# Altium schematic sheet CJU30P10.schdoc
size 127 x 101 mm
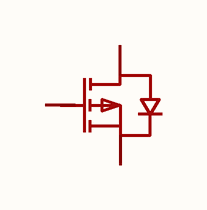
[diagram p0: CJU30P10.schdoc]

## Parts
Q?  cju30p10  [TO-252-2_L6.6-W6.1-P4.57-LS10.1-BL]  (value not drawn)

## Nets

Not connected (* = marked no-connect by the designer): Q? 1(G) 2(S) 3(D)

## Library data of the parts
Q? = cju30p10: 数量:1个P沟道;漏源电压(Vdss):100V;连续漏极电流(Id):30A;导通电阻(RDS(on)):55mΩ@4.5V;耗散功率(Pd):108W;阈值电压(Vgs(th)):2.5V;; Manufacturer: CJ(江苏长电/长晶); AddInBom: yes; ModelId: b8490bd177664f85abc7dca42f3ee0d2; ModelTransform: 259.842,397.637,0,0,0,0,-0.001,39.17,0; Number: 1个P沟道; Drain to Source Voltage: 100V; Current - Continuous Drain(Id): 30A; Pd - Power Dissipation: 108W; Gate Threshold Voltage (Vgs(th)): 2.5V; Gate Charge(Qg): 196nC@10V; Input Capacitance(Ciss): 12.63nF; Reverse Transfer Capacitance (Crss@Vds): 100pF; Type: P沟道; Output Capacitance(Coss): 440pF; Vgs: ±20V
